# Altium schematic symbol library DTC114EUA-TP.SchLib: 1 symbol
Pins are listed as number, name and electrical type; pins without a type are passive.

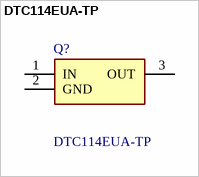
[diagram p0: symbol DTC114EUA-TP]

## DTC114EUA-TP
designator Q?
Pre-Biased Transistors; Manufacturer_Name: MCC; Geometry.Height: 1.2mm
footprint SOT65P228X120-3N
pins: 1 IN, 2 GND, 3 OUT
